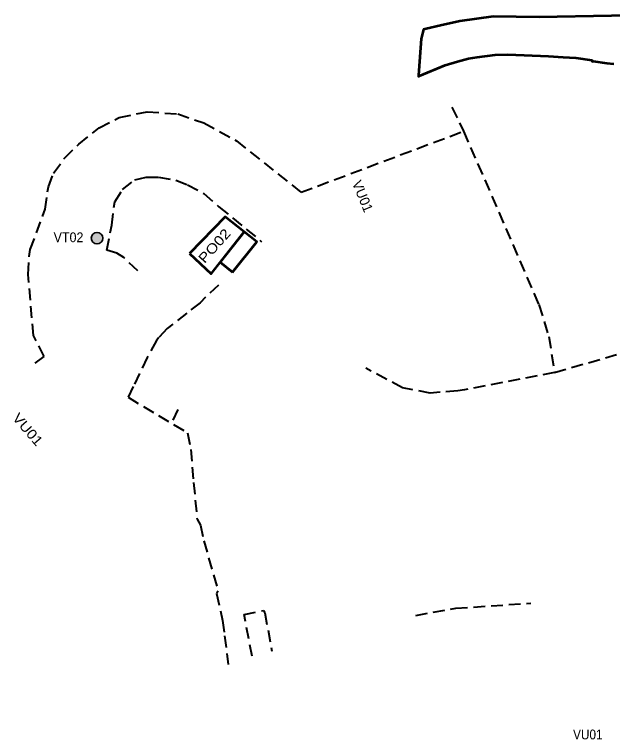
# Model space of a CAD drawing. Extents: x -650145 to -642675, y -1074338 to -1066724.
# Drawn here: x -650145 to -648927, y -1070645 to -1069167 of the extents above; entities that cross this region are included whole.
import ezdxf

# ---------------------------------------------------------------- set-up
doc = ezdxf.new("R2010")
doc.units = 0
doc.header["$LTSCALE"] = 8
doc.linetypes.add('MEDIUM_DASHED', pattern=[4.5, 3, -1.5])
for name, color, linetype, lineweight in [('12', 7, 'MEDIUM_DASHED', 40), ('15', 7, 'Continuous', 13), ('45', 7, 'Continuous', 53), ('46', 7, 'Continuous', 53)]:
    doc.layers.add(name, color=color, linetype=linetype, lineweight=lineweight)
for name, color, linetype in [('17', 7, 'Continuous'), ('2', 7, 'Continuous'), ('5', 7, 'Continuous')]:
    doc.layers.add(name, color=color, linetype=linetype)

msp = doc.modelspace()

# ---------------------------------------------------------------- hatches: boundary and pattern name
at = {"layer": '15'}
msp.add_hatch(color=256, dxfattribs=at).paths.add_polyline_path([(-649965.367, -1069623.362, 1), (-649988.892, -1069623.362, 1)])

# ---------------------------------------------------------------- linework, layer by layer
at = {"layer": '12'}
for p, q in [((-649561.229, -1069529.679), (-649230.09, -1069405.382)), ((-649812.401, -1069972.556), (-649825.281, -1070000.693))]:
    msp.add_line(p, q, dxfattribs=at)
for points in [[(-650103.474, -1069877.787), (-650084.938, -1069864.261), (-650106.91, -1069821.516), (-650117.539, -1069697.081), (-650115.437, -1069660.575), (-650113.146, -1069646.371), (-650082.659, -1069564.521), (-650076.339, -1069518.627), (-650065.774, -1069491.142), (-650043.673, -1069460), (-650014.541, -1069431.96), (-649972.852, -1069398.452), (-649931.689, -1069377.161), (-649874.912, -1069365.805), (-649812.457, -1069370.063), (-649759.229, -1069388.516), (-649693.075, -1069424.839), (-649561.229, -1069529.679)], [(-649253.852, -1069356.119), (-649230.09, -1069405.382), (-649076.593, -1069758.743), (-649056.232, -1069823.932), (-649044.908, -1069897.057), (-649228.331, -1069932.561), (-649242.081, -1069934.228), (-649297.984, -1069939.047), (-649354.851, -1069928.445), (-649429.2, -1069888.2)], [(-649894.276, -1069689.929), (-649922.552, -1069662.785), (-649936.52, -1069654.039), (-649956.998, -1069647.787), (-649947.192, -1069596.622), (-649941.165, -1069549.407), (-649925.091, -1069524.293), (-649899.977, -1069504.201), (-649876.871, -1069499.178), (-649851.757, -1069499.178), (-649816.353, -1069505.42), (-649792.712, -1069514.367), (-649759.641, -1069532.282), (-649728.567, -1069559.269), (-649641.664, -1069630.461)], [(-649729.723, -1069719.048), (-649767.23, -1069754.779), (-649794.247, -1069776.092), (-649834.299, -1069807.359), (-649851.029, -1069825.755), (-649856.254, -1069832.159), (-649875.133, -1069866.696), (-649903.303, -1069925.944), (-649913.581, -1069947.56), (-649793.063, -1070020.079), (-649786.071, -1070054.229), (-649780.314, -1070121.295), (-649773.322, -1070195.767), (-649766.003, -1070207.927), (-649759.422, -1070240.431), (-649730.633, -1070342.059), (-649733.512, -1070347.819), (-649721.595, -1070402.368), (-649717.071, -1070434.049), (-649709.95, -1070492.08)], [(-649044.908, -1069897.057), (-648493.206, -1069738.027), (-648473.126, -1069807.804), (-648452.457, -1069825.52), (-648407.58, -1069817.388), (-648283.564, -1069782.827)], [(-649327.442, -1070392.02), (-649245.779, -1070377.706), (-649092.777, -1070367.093)], [(-649661.13, -1070475.457), (-649677.337, -1070390.592), (-649637.948, -1070382.008), (-649634.895, -1070386.757), (-649621.153, -1070465.046)]]:
    msp.add_lwpolyline(points, dxfattribs=at)
at = {"layer": '15', "lineweight": 35}
msp.add_circle((-649977.129, -1069623.362), 11.762, dxfattribs=at)
at = {"layer": '45'}
msp.add_lwpolyline([(-648781.015, -1069167.44), (-649076.02, -1069172.683), (-649169.781, -1069171.432), (-649237.512, -1069180.731), (-649277.021, -1069189.913), (-649306.455, -1069196.754), (-649311.633, -1069197.958), (-649316.47, -1069216.91), (-649321.32, -1069281.47), (-649322.09, -1069291.73), (-649322.22, -1069293.54), (-649319.72, -1069292.47), (-649267.5, -1069270.41), (-649242.5, -1069263.3), (-649220.18, -1069257.03), (-649202.63, -1069254.4), (-649165.62, -1069249.43), (-649139.63, -1069248.73), (-649056.95, -1069252.55), (-649026.955, -1069254.366), (-649001.3, -1069255.92), (-648968.49, -1069260.36), (-648968.05, -1069263.06), (-648965.8, -1069262.75), (-648937.91, -1069266.51), (-648924.13, -1069268.21)], dxfattribs=at)
at = {"layer": '46'}
for points in [[(-649788.91, -1069654.4), (-649744.517, -1069695.746), (-649677.124, -1069610.681), (-649715.908, -1069579.804)], [(-649701.211, -1069692.826), (-649651.773, -1069630.879), (-649677.124, -1069610.681), (-649726.033, -1069672.415)]]:
    msp.add_lwpolyline(points, close=True, dxfattribs=at)

# ---------------------------------------------------------------- texts
at = {"layer": '17', "width": 0.95}
msp.add_text('VT02', height=20, dxfattribs=at).set_placement((-650065.613, -1069631.552))
at = {"layer": '2'}
msp.add_text('VU01', height=20, rotation=292.277, dxfattribs=at).set_placement((-649457.739, -1069510.652))
at = {"layer": '2', "width": 1.15}
msp.add_text('VU01', height=20, rotation=310.892, dxfattribs=at).set_placement((-650151.079, -1069990.662))
at = {"layer": '2', "width": 0.9}
msp.add_text('VU01', height=20, dxfattribs=at).set_placement((-649006.975, -1070644.798))
at = {"layer": '5', "width": 1.2}
msp.add_text('PO02', height=20, rotation=48.242, dxfattribs=at).set_placement((-649757.728, -1069676.189))

doc.saveas('drawing.dxf')
